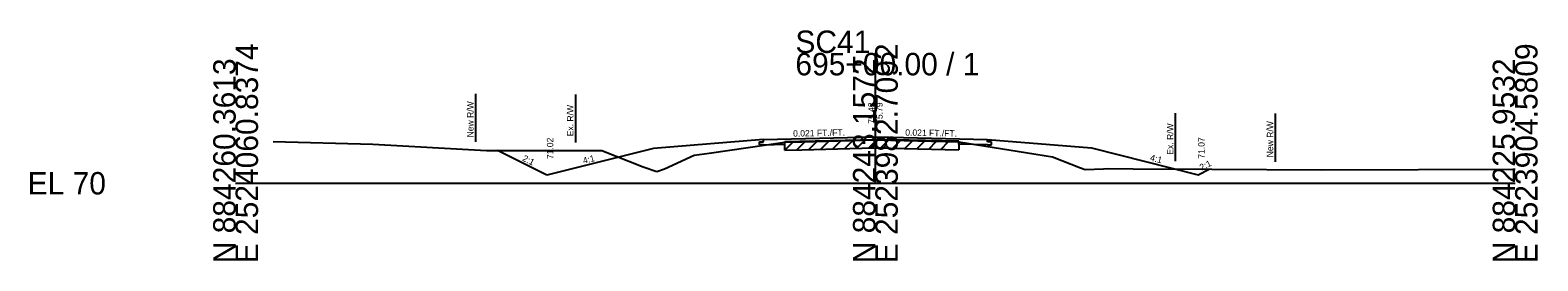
# Model space of a CAD drawing. Extents: x -26 to 183, y -10 to 24021.
# Drawn here: x -25.7 to 162.8, y 19490.3 to 19519.1 of the extents above; entities that cross this region are included whole.
import ezdxf

# ---------------------------------------------------------------- set-up
doc = ezdxf.new("R2010")
doc.units = 0
for name, color, linetype in [('RD_GPK_XS_Cell', 7, 'Continuous'), ('RD_XS_Base', 7, 'Continuous'), ('RD_XS_Buildup', 7, 'Continuous'), ('RD_XS_EarthShd', 7, 'Continuous'), ('RD_XS_ExGround', 7, 'Continuous'), ('RD_XS_ExPaveRet', 7, 'Continuous'), ('RD_XS_ExRW', 7, 'Continuous'), ('RD_XS_NewRW', 7, 'Continuous'), ('RD_XS_Pave', 7, 'Continuous'), ('RD_XS_TieSlope', 7, 'Continuous'), ('RD_XS_TX_Elev_EX', 7, 'Continuous'), ('RD_XS_TX_Elev_PR', 7, 'Continuous'), ('RD_XS_TX_Slope', 7, 'Continuous')]:
    doc.layers.add(name, color=color, linetype=linetype)

msp = doc.modelspace()

# ---------------------------------------------------------------- linework, layer by layer
at = {"layer": 'RD_GPK_XS_Cell'}
for p, q in [((80, 19500), (80, 19516.29)), ((0, 19500), (80, 19500)), ((80, 19500), (160, 19500))]:
    msp.add_line(p, q, dxfattribs=at)
at = {"layer": 'RD_XS_Base'}
for p, q in [((66, 19504.81), (68.67, 19504.87)), ((68.67, 19504.87), (68.67, 19505.13)), ((90.44, 19504.89), (90.44, 19505.18)), ((94, 19504.81), (90.44, 19504.89))]:
    msp.add_line(p, q, dxfattribs=at)
at = {"layer": 'RD_XS_Buildup'}
for p, q in [((68.67, 19505.23), (80, 19505.47)), ((68.67, 19505.13), (68.67, 19505.23)), ((90.44, 19505.25), (80, 19505.47)), ((90.44, 19505.18), (90.44, 19505.25))]:
    msp.add_line(p, q, dxfattribs=at)
at = {"layer": 'RD_XS_EarthShd'}
for p, q in [((66, 19505.49), (52.26, 19504.35)), ((94, 19505.49), (107.04, 19504.41))]:
    msp.add_line(p, q, dxfattribs=at)
at = {"layer": 'RD_XS_ExGround'}
for p, q in [((4.7, 19505.23), (17.17, 19504.89)), ((17.17, 19504.89), (31.36, 19504.1)), ((31.36, 19504.1), (41.29, 19504.09)), ((41.29, 19504.09), (45.79, 19504.08)), ((45.79, 19504.08), (50.98, 19502.07)), ((57.34, 19503.53), (59.2, 19503.78)), ((59.2, 19503.78), (68.67, 19505.13)), ((68.67, 19505.13), (70.81, 19505.18)), ((70.81, 19505.18), (79.8, 19505.43)), ((79.8, 19505.43), (81.91, 19505.38)), ((81.91, 19505.38), (90.44, 19505.18)), ((90.44, 19505.18), (100.07, 19503.64)), ((50.98, 19502.07), (52.68, 19501.48)), ((52.68, 19501.48), (53.61, 19501.82)), ((53.61, 19501.82), (57.34, 19503.53)), ((100.07, 19503.64), (102.15, 19503.31)), ((102.15, 19503.31), (105.63, 19501.95)), ((105.63, 19501.95), (106.25, 19501.72)), ((108.53, 19501.79), (109.03, 19501.84)), ((109.03, 19501.84), (112.25, 19501.82)), ((112.25, 19501.82), (122.08, 19501.75)), ((106.25, 19501.72), (108.53, 19501.79)), ((122.08, 19501.75), (135.8, 19501.67)), ((135.8, 19501.67), (160, 19501.75))]:
    msp.add_line(p, q, dxfattribs=at)
at = {"layer": 'RD_XS_ExPaveRet'}
for p, q in [((68.67, 19504.13), (69.69, 19505.15)), ((68.67, 19504.13), (68.67, 19505.13)), ((68.67, 19504.13), (70.81, 19504.18)), ((70.17, 19504.17), (71.19, 19505.19)), ((70.81, 19504.18), (79.8, 19504.43)), ((71.67, 19504.21), (72.69, 19505.24)), ((73.17, 19504.25), (74.19, 19505.28)), ((74.67, 19504.29), (75.69, 19505.32)), ((76.17, 19504.33), (77.19, 19505.36)), ((77.67, 19504.37), (78.69, 19505.4)), ((79.17, 19504.41), (80.17, 19505.42)), ((79.8, 19504.43), (81.91, 19504.38)), ((80.67, 19504.41), (81.64, 19505.39)), ((81.91, 19504.38), (90.44, 19504.18)), ((82.17, 19504.38), (83.14, 19505.35)), ((83.67, 19504.34), (84.64, 19505.32)), ((85.17, 19504.3), (86.14, 19505.28)), ((86.67, 19504.27), (87.64, 19505.25)), ((88.17, 19504.23), (89.14, 19505.21)), ((90.44, 19505.18), (90.44, 19504.18))]:
    msp.add_line(p, q, dxfattribs=at)
at = {"layer": 'RD_XS_ExRW'}
for p, q in [((42.5, 19511.09), (42.5, 19505.09)), ((117.5, 19508.78), (117.5, 19502.78))]:
    msp.add_line(p, q, dxfattribs=at)
at = {"layer": 'RD_XS_NewRW'}
for p, q in [((30, 19511.18), (30, 19505.18)), ((130, 19508.7), (130, 19502.7))]:
    msp.add_line(p, q, dxfattribs=at)
at = {"layer": 'RD_XS_Pave'}
for p, q in [((66, 19505.49), (80, 19505.79)), ((80, 19505.79), (94, 19505.49)), ((65.5, 19505.16), (66, 19505.17)), ((65.5, 19504.8), (65.5, 19505.16)), ((66, 19504.81), (65.5, 19504.8)), ((66, 19505.17), (66, 19505.49)), ((94, 19505.17), (94, 19505.49)), ((94.5, 19505.16), (94, 19505.17)), ((94, 19504.81), (94.5, 19504.8)), ((94.5, 19504.8), (94.5, 19505.16))]:
    msp.add_line(p, q, dxfattribs=at)
at = {"layer": 'RD_XS_TieSlope'}
for p, q in [((38.92, 19501.02), (32.75, 19504.1)), ((52.26, 19504.35), (38.92, 19501.02)), ((107.04, 19504.41), (120.37, 19501.07)), ((120.37, 19501.07), (121.73, 19501.75))]:
    msp.add_line(p, q, dxfattribs=at)

# ---------------------------------------------------------------- texts
at = {"layer": 'RD_GPK_XS_Cell'}
for s, p in [('SC41', (70, 19516.29)), ('695+00.00 / 1', (70, 19513.49)), ('EL 70', (-26, 19498.6))]:
    msp.add_text(s, height=2.8, dxfattribs=at).set_placement(p)
for s, p in [('E 2524060.8374', (2.8, 19490)), ('E 2523982.7092', (82.8, 19490)), ('E 2523904.5809', (162.8, 19490)), ('N 884260.3613', (0, 19490)), ('N 884243.1572', (80, 19490)), ('N 884225.9532', (160, 19490))]:
    msp.add_text(s, height=2.8, rotation=90, dxfattribs=at).set_placement(p)
at = {"layer": 'RD_XS_ExRW'}
for p in [(42.25, 19505.87), (117.25, 19503.57)]:
    msp.add_text('Ex. R/W ', height=0.8, rotation=90, dxfattribs=at).set_placement(p)
at = {"layer": 'RD_XS_NewRW'}
for p in [(29.75, 19505.73), (129.75, 19503.25)]:
    msp.add_text('New R/W ', height=0.8, rotation=90, dxfattribs=at).set_placement(p)
at = {"layer": 'RD_XS_TX_Elev_EX'}
msp.add_text('75.43', height=0.8, rotation=90, dxfattribs=at).set_placement((79.9, 19507.43))
at = {"layer": 'RD_XS_TX_Elev_PR'}
for s, p in [('75.79', (80.9, 19507.43)), ('71.02', (39.72, 19503.02)), ('71.07', (121.17, 19503.07))]:
    msp.add_text(s, height=0.8, rotation=90, dxfattribs=at).set_placement(p)
at = {"layer": 'RD_XS_TX_Slope'}
for s, rotation, p in [('0.021 FT./FT.', 1.1916, (69.72, 19505.82)), ('0.021 FT./FT.', 358.8084, (83.73, 19505.96)), ('2:1', 333.4349, (35.79, 19502.86)), ('4:1', 14.0362, (43.53, 19502.42)), ('4:1', 345.9638, (114.3, 19502.85)), ('2:1', 26.5651, (120.79, 19501.56))]:
    msp.add_text(s, height=0.8, rotation=rotation, dxfattribs=at).set_placement(p)

doc.saveas('drawing.dxf')
